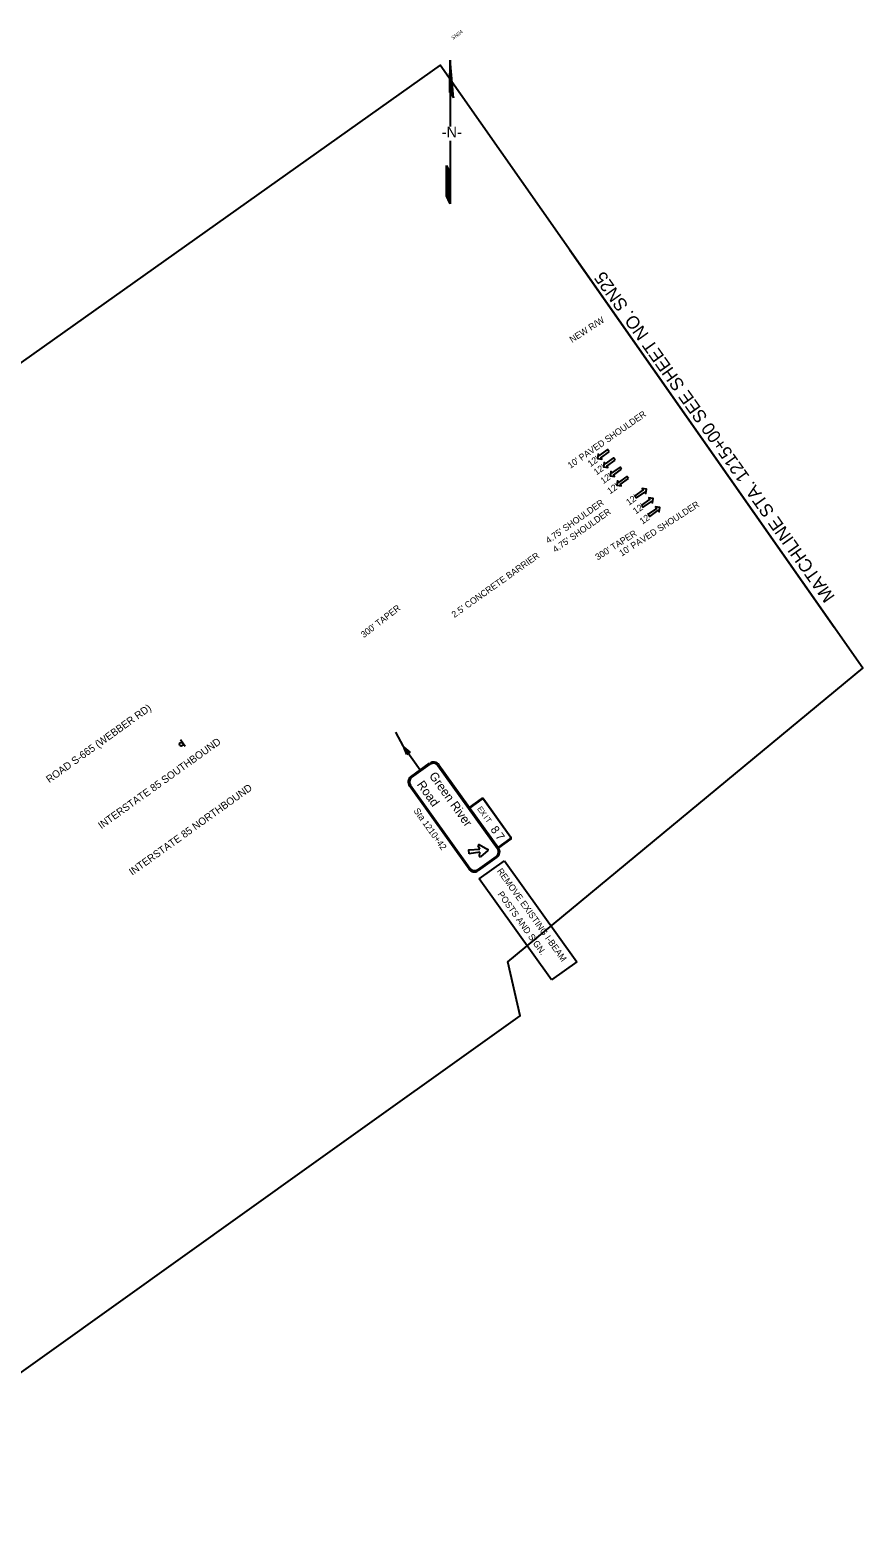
# Model space of a CAD drawing. Extents: x 1769713 to 1771399, y 1177155 to 1178792.
# Drawn here: x 1770495 to 1771399, y 1177155 to 1178792 of the extents above; entities that cross this region are included whole.
import ezdxf

# ---------------------------------------------------------------- set-up
doc = ezdxf.new("R2010")
doc.units = 0
for name, color, linetype in [('RD_EX_BldgApp', 7, 'Continuous'), ('RD_HC_Data', 7, 'Continuous'), ('RD_PD_FOC', 7, 'Continuous'), ('RD_PD_GR', 7, 'Continuous'), ('RD_PD_MedBWall', 7, 'Continuous'), ('RD_PD_PaveShd', 7, 'Continuous'), ('RD_QTY_GR', 7, 'Continuous'), ('RD_SHT_MatchLine', 7, 'Continuous'), ('RD_Sketch1', 7, 'Continuous'), ('RD_TX_RoadID', 7, 'Continuous')]:
    doc.layers.add(name, color=color, linetype=linetype)

# ---------------------------------------------------------------- blocks, each defined once
blk = doc.blocks.new('NA5')
at = {"layer": 'RD_Sketch1'}
for p, q in [((47.5, 65.9), (26.8, 37.4)), ((26.8, 30.6), (47.5, 65.9)), ((27.2, 37.5), (14.5, 19.8)), ((28.1, 38.3), (26.8, 30.6)), ((14.5, 19.8), (5.5, 7.2)), ((-3.5, -5.3), (-18.5, -26.3)), ((-18.5, -26.3), (-43.3, -60.9)), ((-30.6, -36.2), (-22.3, -24.7)), ((-22.3, -24.7), (-24, -34)), ((-41.6, -51.6), (-30.6, -36.2)), ((-43.3, -60.9), (-41.6, -51.6))]:
    blk.add_line(p, q, dxfattribs=at)
for points in [[(27.4, 37.8), (47.4, 65.8)], [(27.1, 37.6), (39.2, 54.5)], [(27.6, 37.9), (46.9, 64.9)], [(27.6, 35.5), (39, 51.5)], [(27.6, 35.3), (38.5, 50.6)], [(27.6, 35.1), (38, 49.7)], [(27.7, 36.2), (40.6, 54.2)], [(27.7, 36), (40.1, 53.3)], [(27.7, 35.8), (39.6, 52.4)], [(27.8, 38.1), (46.4, 64)], [(27.8, 36.8), (42.2, 56.8)], [(27.8, 36.6), (41.7, 56)], [(27.8, 36.4), (41.1, 55.1)], [(27.9, 37.4), (43.8, 59.5)], [(27.9, 37.2), (43.2, 58.6)], [(27.9, 37), (42.7, 57.7)], [(28, 38.1), (45.3, 62.2)], [(28, 37.9), (44.8, 61.3)], [(28, 37.7), (44.3, 60.4)], [(28.1, 38.3), (45.8, 63.1)], [(26.9, 37.5), (29.9, 41.7)], [(26.9, 31.3), (28.5, 33.6)], [(27, 32), (30.1, 36.3)], [(27, 31.8), (29.6, 35.4)], [(27, 31.5), (29.1, 34.5)], [(27.1, 32.6), (31.7, 39)], [(27.1, 32.4), (31.2, 38.1)], [(27.1, 32.2), (30.6, 37.2)], [(27.2, 33.2), (33.3, 41.6)], [(27.2, 33), (32.7, 40.7)], [(27.2, 32.8), (32.2, 39.9)], [(27.3, 33.9), (34.8, 44.3)], [(27.3, 33.7), (34.3, 43.4)], [(27.3, 33.4), (33.8, 42.5)], [(27.4, 34.5), (36.4, 47)], [(27.4, 34.3), (35.9, 46.1)], [(27.4, 34.1), (35.4, 45.2)], [(27.5, 34.9), (37.5, 48.8)], [(27.5, 34.7), (36.9, 47.9)], [(26.8, 30.7), (27, 30.9)], [(26.9, 31.1), (28, 32.7)], [(26.9, 30.9), (27.5, 31.8)], [(-43, -59), (-23.7, -32.1)], [(-43, -59.2), (-23.7, -32.3)], [(-43, -59.4), (-23.8, -32.5)], [(-42.9, -58.6), (-23.6, -31.7)], [(-42.9, -58.8), (-23.7, -31.9)], [(-42.8, -58.1), (-23.5, -31.2)], [(-42.8, -58.3), (-23.6, -31.4)], [(-42.7, -57.5), (-23.4, -30.6)], [(-42.7, -57.7), (-23.5, -30.8)], [(-42.7, -57.9), (-23.5, -31)], [(-42.6, -57), (-23.3, -30.1)], [(-42.6, -57.2), (-23.4, -30.4)], [(-42.5, -56.4), (-23.2, -29.5)], [(-42.5, -56.6), (-23.2, -29.7)], [(-42.5, -56.8), (-23.3, -29.9)], [(-42.4, -55.9), (-23.1, -29)], [(-42.4, -56.1), (-23.2, -29.3)], [(-42.3, -55.3), (-23, -28.4)], [(-42.3, -55.5), (-23, -28.6)], [(-42.3, -55.7), (-23.1, -28.8)], [(-42.2, -54.8), (-22.9, -27.9)], [(-42.2, -55), (-23, -28.2)], [(-42.1, -54.4), (-22.8, -27.5)], [(-42.1, -54.6), (-22.9, -27.7)], [(-42, -53.7), (-22.7, -26.8)], [(-42, -53.9), (-22.7, -27.1)], [(-42, -54.2), (-22.8, -27.3)], [(-41.9, -53.3), (-22.6, -26.4)], [(-41.9, -53.5), (-22.7, -26.6)], [(-41.8, -52.6), (-22.5, -25.7)], [(-41.8, -52.8), (-22.5, -26)], [(-41.8, -53.1), (-22.6, -26.2)], [(-41.7, -52.2), (-22.4, -25.3)], [(-41.7, -52.4), (-22.5, -25.5)], [(-41.6, -51.7), (-22.3, -24.9)], [(-41.6, -52), (-22.4, -25.1)], [(-43.3, -60.8), (-24, -33.9)], [(-43.2, -60.1), (-23.9, -33.2)], [(-43.2, -60.3), (-23.9, -33.4)], [(-43.2, -60.5), (-24, -33.6)], [(-43.1, -59.7), (-23.8, -32.8)], [(-43.1, -59.9), (-23.9, -33)]]:
    blk.add_lwpolyline(points, dxfattribs=at)
blk.add_text('-N-', height=11.81, rotation=324.3865, dxfattribs=at).set_placement((-8.8, 3))
blk = doc.blocks.new('SARRW2')
at = {"layer": 'RD_PD_GR'}
blk.add_lwpolyline([(-12, 1.2), (-12, -1.2), (-2.8, -1.2), (-2.8, -2.8), (0, 0), (-2.8, 2.8), (-2.8, 1.2)], close=True, dxfattribs=at)

msp = doc.modelspace()

# ---------------------------------------------------------------- linework, layer by layer
at = {"layer": 'RD_EX_BldgApp'}
msp.add_line((1770663.4, 1178014.1), (1770658.1, 1178021.4), dxfattribs=at)
msp.add_circle((1770659.1, 1178016.6), 2, dxfattribs=at)
at = {"layer": 'RD_HC_Data'}
msp.add_lwpolyline([(1770233.7, 1177155.2), (1770800.5, 1177559.9), (1771027.1, 1177721.7), (1771013.4, 1177780.4), (1771398.9, 1178099.1), (1771333.7, 1178192), (1771094.5, 1178533.3), (1770940, 1178753.7), (1769712.5, 1177882.8), (1769897.9, 1177624), (1770003.7, 1177476.3), (1770123.1, 1177309.6)], close=True, dxfattribs=at)
at = {"layer": 'RD_PD_FOC'}
for p, q in [((1770891.5, 1178029.6), (1770899.9, 1178014.3)), ((1770663.4, 1178014.1), (1770658.1, 1178021.4)), ((1770918.5, 1177988.6), (1770900.8, 1178013.4)), ((1770908.4, 1177981.3), (1770928.7, 1177995.9)), ((1770909.1, 1177980.4), (1770929.4, 1177994.9)), ((1771001, 1177894.9), (1770980.7, 1177880.4)), ((1771001.7, 1177893.9), (1770981.4, 1177879.4)), ((1770982.5, 1177870.5), (1771009.8, 1177890.1)), ((1771009.8, 1177890.1), (1771088.4, 1177780.3)), ((1771061.1, 1177760.7), (1770982.5, 1177870.5)), ((1771088.4, 1177780.3), (1771061.1, 1177760.7))]:
    msp.add_line(p, q, dxfattribs=at)
msp.add_lwpolyline([(1770904, 1178005.6), (1770900.8, 1178013.4), (1770907.3, 1178008)], close=True, dxfattribs=at)
for points in [[(1770937.7, 1177993.5), (1771002.3, 1177903.3)], [(1770938.7, 1177994.2), (1771003.3, 1177904)], [(1770971.4, 1177881.1), (1770906.7, 1177971.3)], [(1770972.3, 1177881.8), (1770907.7, 1177972)], [(1770985.4, 1177956.8), (1770972.2, 1177947.4), (1770971.9, 1177947.9), (1770985.1, 1177957.3)], [(1771016.4, 1177915.6), (1770987.1, 1177956.5)], [(1770987.6, 1177956.9), (1771016.9, 1177915.9)], [(1771003, 1177904.5), (1771016.2, 1177913.9)], [(1771016.5, 1177913.4), (1771003.3, 1177904), (1771003, 1177904.5)], [(1770971.5, 1177897.8), (1770971.1, 1177902), (1770983, 1177902.6)], [(1770983.3, 1177899.4), (1770971.5, 1177897.8)], [(1770983, 1177902.6), (1770981.5, 1177906.8)], [(1770982.4, 1177907.6), (1770991.9, 1177902.4)], [(1770982.7, 1177895), (1770983.3, 1177899.4)], [(1770992, 1177901.4), (1770983.7, 1177894.5)]]:
    msp.add_lwpolyline(points, dxfattribs=at)
msp.add_circle((1770659.1, 1178016.6), 2, dxfattribs=at)
for centre, radius, start, end in [((1770932.9, 1177990), 7.2, 35.6135, 125.6135), ((1770932.9, 1177990), 6, 35.6135, 125.6135), ((1770912.6, 1177975.5), 7.2, 125.6135, 215.6135), ((1770912.6, 1177975.5), 6, 125.6135, 215.6135), ((1770986.1, 1177955.8), 1.8, 35.6135, 125.6135), ((1770986.1, 1177955.8), 1.2, 35.6135, 125.6135), ((1771015.5, 1177914.9), 1.2, 305.6135, 35.6135), ((1771015.5, 1177914.9), 1.8, 305.6135, 35.6135), ((1770982.1, 1177907), 0.6, 61.5942, 199.0596), ((1770983.3, 1177894.9), 0.6, 172.1674, 309.6329), ((1770991.6, 1177901.9), 0.6, 309.6329, 61.5942), ((1770997.5, 1177899.8), 6, 305.6135, 35.6135), ((1770997.5, 1177899.8), 7.2, 305.6135, 35.6135), ((1770977.2, 1177885.3), 7.2, 215.6135, 305.6135), ((1770977.2, 1177885.3), 6, 215.6135, 305.6135)]:
    msp.add_arc(centre, radius, start, end, dxfattribs=at)
at = {"layer": 'RD_SHT_MatchLine'}
msp.add_lwpolyline([(1771367.9, 1178143.2), (1771224.4, 1178347.9), (1771080.9, 1178552.6)], dxfattribs=at)

# ---------------------------------------------------------------- block references
at = {"layer": 'RD_PD_GR', "xscale": 1.1999999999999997}
for p, yscale, rotation in [((1771110.9, 1178326.8), 1.2000000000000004, -144.38650217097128), ((1771117.4, 1178317.8), 1.2000000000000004, -144.38650217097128), ((1771124.5, 1178307.9), 1.2000000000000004, -144.38650217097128), ((1771131.8, 1178297.7), 1.2000000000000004, -144.38650217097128), ((1771164, 1178293.5), 1.2, 35.61349782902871), ((1771171.3, 1178283.3), 1.2, 35.61349782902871), ((1771178.4, 1178273.4), 1.2, 35.61349782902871)]:
    msp.add_blockref('SARRW2', p, dxfattribs=dict(at, yscale=yscale, rotation=rotation))
at = {"layer": 'RD_SHT_MatchLine', "rotation": 35.61349782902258}
msp.add_blockref('NA5', (1770950.6, 1178677.9), dxfattribs=at)

# ---------------------------------------------------------------- texts
at = {"layer": 'RD_PD_FOC'}
for s, height, rotation, p in [('Road', 9.6, 305.6135, (1770914.3, 1177972.8)), ('Green River', 9.6, 305.6135, (1770927.6, 1177982.3)), ('Sta 1210+42', 7, 305.6136, (1770910.9, 1177944.3)), ('E', 6, 305.6135, (1770979.9, 1177946.5)), ('X', 6, 305.6135, (1770982.9, 1177942.3)), ('I', 6, 305.6135, (1770986.8, 1177936.8)), ('T', 6, 305.6135, (1770988.6, 1177934.4)), ('8', 9, 305.6135, (1770994.3, 1177923.9)), ('7', 9, 305.6135, (1770999.6, 1177916.5)), ('REMOVE EXISTING I-BEAM', 7, 305.6136, (1771001.4, 1177878.8)), ('POSTS AND SIGN.', 7, 305.6136, (1771002.1, 1177853.8))]:
    msp.add_text(s, height=height, rotation=rotation, dxfattribs=at).set_placement(p)
at = {"layer": 'RD_PD_MedBWall'}
for s, rotation, p in [("10' PAVED SHOULDER", 34.8965, (1771081.5, 1178315.5)), ("12'", 35.6135, (1771103.3, 1178317.3)), ("12'", 35.6135, (1771109.8, 1178308.3)), ("12'", 35.6135, (1771117.2, 1178298.8)), ("12'", 35.6135, (1771124.5, 1178287.7)), ("12'", 35.6135, (1771145, 1178275.4)), ("4.75' SHOULDER", 35.4379, (1771057.7, 1178234.1)), ("4.75' SHOULDER", 35.4379, (1771065.3, 1178224.3)), ("10' PAVED SHOULDER", 32.8728, (1771137.2, 1178220.2)), ("12'", 35.6135, (1771152.4, 1178265.9)), ("12'", 35.6135, (1771159.7, 1178254.9)), ("300' TAPER", 32.7634, (1771111.2, 1178216)), ("2.5' CONCRETE BARRIER", 35.4379, (1770955.6, 1178153.6)), ("300' TAPER", 37.8494, (1770857.3, 1178131.7))]:
    msp.add_text(s, height=7, rotation=rotation, dxfattribs=at).set_placement(p)
at = {"layer": 'RD_PD_PaveShd'}
msp.add_text('SN24', height=4, rotation=35.5257, dxfattribs=at).set_placement((1770954, 1178781.1))
at = {"layer": 'RD_QTY_GR'}
msp.add_text('NEW R/W', height=7, rotation=32.9631, dxfattribs=at).set_placement((1771083.3, 1178452.1))
at = {"layer": 'RD_SHT_MatchLine'}
msp.add_text('MATCHLINE STA. 1215+00 SEE SHEET NO. SN25', height=14, rotation=125.3542, dxfattribs=at).set_placement((1771369.1, 1178176.8))
at = {"layer": 'RD_TX_RoadID'}
for s, rotation, p in [('ROAD S-665 (WEBBER RD)', 35.6984, (1770515.9, 1177974.2)), ('INTERSTATE 85 SOUTHBOUND', 35.6135, (1770572.4, 1177924.2)), ('INTERSTATE 85 NORTHBOUND', 35.6135, (1770605.9, 1177873.8))]:
    msp.add_text(s, height=8, rotation=rotation, dxfattribs=at).set_placement(p)

doc.saveas('drawing.dxf')
